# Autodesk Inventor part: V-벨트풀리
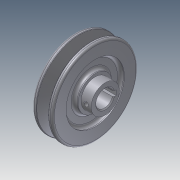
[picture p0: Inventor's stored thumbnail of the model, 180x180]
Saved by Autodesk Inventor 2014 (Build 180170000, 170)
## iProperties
Company: 한국ATC센터
Created: 2014-07
Part Number: V-벨트풀리
Document SubType Name: Modeling
Designer: KYOUNG IL JANG
Density: 7.86 g/cm^3
Material: 강, 연강
Mass: 593.012 g
Surface Area: 234.121 cm^2
Volume: 75.4468 cm^3
Appearance: 강철
Author: KYOUNG IL JANG
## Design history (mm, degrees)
sketch "스케치1"
  geometry: L1 (-15, 0)-(15, 0); L2 (-15, 0)-(-15, 17); L3 (-15, 17)-(-11, 17); L4 (-11, 17)-(-11, 29); L5 (-11, 29)-(-15, 29); L6 (-15, 29)-(-15, 42.5); L7 (-15, 42.5)-(-10.976, 42.5); L8 (-10.976, 42.5)-(-7.154, 30); L9 (-7.154, 30)-(-2.846, 30); L10 (-2.846, 30)-(0.976, 42.5); L11 (0.976, 42.5)-(5, 42.5); L12 (5, 42.5)-(5, 29); L13 (5, 29)-(1, 29); L14 (1, 29)-(1, 17); L15 (1, 17)-(5, 17); L16 (5, 17)-(5, 14); L17 (5, 14)-(15, 14); L18 (15, 14)-(15, 0); L19 (-9.6, 38)-(-0.4, 38); 2 further points
  constraints: 38 end point, 11 parallel, 7 collinear, 3 equal length, 3 perpendicular, 2 point on line, 1 coincident, 1 horizontal, 1 midpoint
  dimensions: "d0" = 30 distance of L1.start L1.end; "d1" = 4.5 distance between parallel lines of L7 L19; "d2" = 8 distance between parallel lines of L9 L19; "d3" = 9.2 distance of L19.start L19.end; "d4" = 34 deg angle of L10 L8; "d5" = 20 distance between parallel lines of L12 L6; "d6" = 76 diameter of L19 L1; "d7" = 4 distance of L2.end L3.end; "d8" = 34 diameter of L3 L1; "d9" = 58 diameter of L5 L1; "d10" = 28 diameter of L17 L1
revolve "회전1" sketch "스케치1" stored, may be unused: angle "d11" = 90 deg
sketch "스케치2"
  geometry: L1 (-2.5, 8.124)-(-2.5, 10.8); L2 (-2.5, 10.8)-(2.5, 10.8); L3 (2.5, 10.8)-(2.5, 8.124); A1 r 8.5 centre (0, 0) between (-2.5, 8.124) and (2.5, 8.124); 1 further point
  constraints: 6 end point, 2 parallel, 2 point on circle, 1 centre point, 1 coincident, 1 horizontal, 1 vertical
  dimensions: "d12" = 17 diameter of A1; "d13" = 5 distance of L1.end L2.end; "d14" = 19.3 dimension on A1 L2 (computed from d12)
extrude "돌출1" cut sketch "스케치2" stored distance "d15" = 10; taper "d16" = 0 deg
chamfer "모따기1" distance "d17" = 1; stored, may be unused: second distance "d18" = 2, angle "d19" = 45 deg
node "작업 평면1"
sketch "스케치3"
  geometry: L1 (5, -14)-(5, 14) reference; 3 further points
  constraints: 1 horizontal alignment, 1 midpoint
  dimensions: "d20" = 5 distance from line of L1 point (0, 0)
hole "구멍1" sketch "스케치3" at (0, 0) diameter "d21" = 3.242; stored, may be unused: countersink angle "d25" = 90 deg, drill point angle "d27" = 118 deg; dims "d22" = 6, "d23" = 4, "d24" = 2, "d26" = 8
fillet "모깎기1" dims "d28" = 3, "d29" = 2, "d30" = 0.5, "d31" = 1
node "솔리드1"
